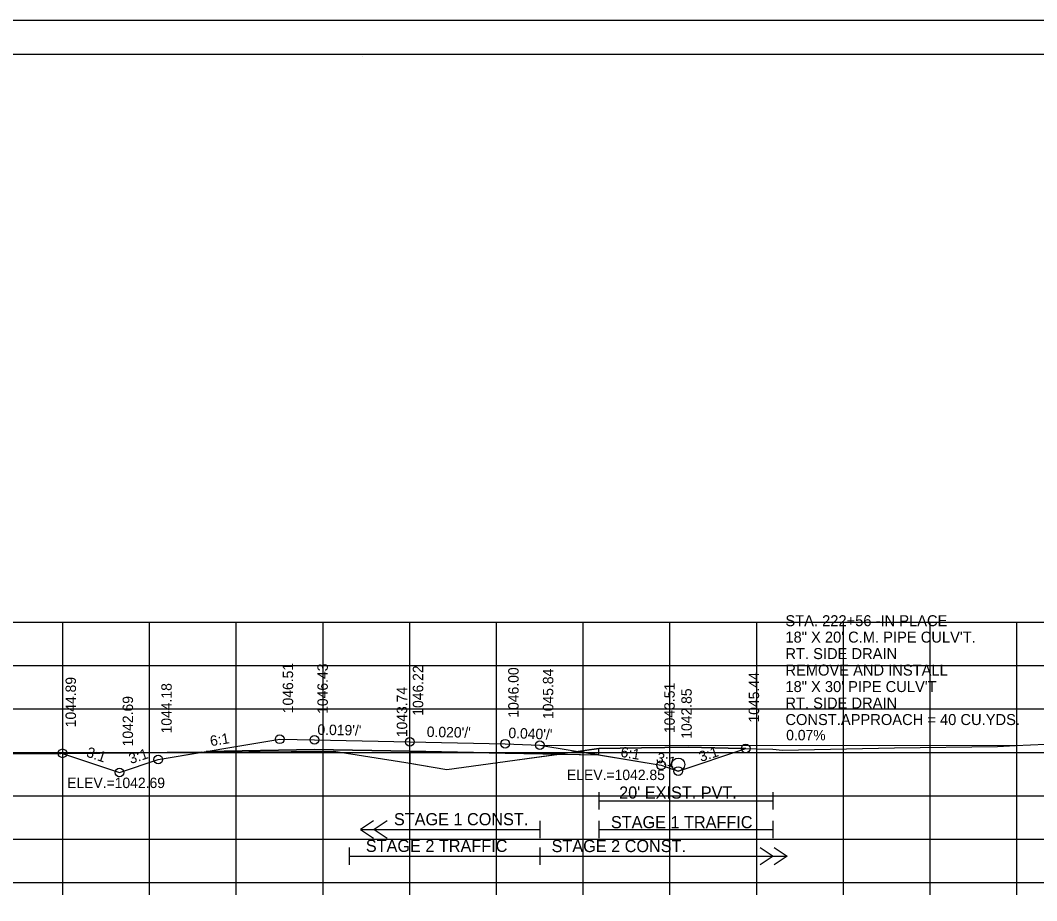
# Model space of a CAD drawing. Extents: x 1370565 to 1374448, y 301010 to 304637.
# Drawn here: x 1373323.9 to 1373441.1, y 303116.9 to 303218.4 of the extents above; entities that cross this region are included whole.
import ezdxf

# ---------------------------------------------------------------- set-up
doc = ezdxf.new("R2010")
doc.units = 0
for name, color, linetype in [('R_Alt Surface', 7, 'Continuous'), ('R_Axis', 7, 'Continuous'), ('R_Axis Annot', 7, 'Continuous'), ('R_Border', 7, 'Continuous'), ('R_Contours', 7, 'Continuous'), ('R_Drive', 7, 'Continuous'), ('R_Exist Surface', 7, 'Continuous'), ('R_Fin Surface', 7, 'Continuous'), ('R_Grid', 7, 'Continuous'), ('R_No Plot', 7, 'Continuous'), ('R_Water', 7, 'Continuous'), ('R_Water Annot', 7, 'Continuous'), ('R_Xsect Elev', 7, 'Continuous'), ('R_Xsect Slope', 7, 'Continuous')]:
    doc.layers.add(name, color=color, linetype=linetype)

msp = doc.modelspace()

# ---------------------------------------------------------------- linework, layer by layer
at = {"layer": 'R_Alt Surface'}
for points in [[(1373345.35, 303134.1), (1373357.81, 303134.35), (1373368.81, 303134.14), (1373379.81, 303133.92), (1373390.66, 303133.7)], [(1373364.62, 303126.12), (1373363.12, 303125.12), (1373364.62, 303124.12)], [(1373366.22, 303126.12), (1373364.72, 303125.12), (1373366.22, 303124.12)], [(1373363.12, 303125.12), (1373383.82, 303125.12)], [(1373361.82, 303123.05), (1373361.82, 303121.05)], [(1373383.82, 303123.05), (1373383.82, 303121.05)], [(1373383.82, 303123.05), (1373383.82, 303121.05)], [(1373409.22, 303123.05), (1373410.72, 303122.05), (1373409.22, 303121.05)], [(1373410.81, 303123.05), (1373412.31, 303122.05), (1373410.81, 303121.05)], [(1373361.82, 303122.05), (1373383.82, 303122.05)], [(1373383.82, 303122.05), (1373412.31, 303122.05)]]:
    msp.add_lwpolyline(points, dxfattribs=at)
at = {"layer": 'R_Axis'}
for p, q in [((1373218.81, 303119), (1373518.81, 303119)), ((1373328.81, 303117.6), (1373328.81, 303119)), ((1373338.81, 303117.6), (1373338.81, 303119)), ((1373348.81, 303117.6), (1373348.81, 303119)), ((1373358.81, 303117.6), (1373358.81, 303119)), ((1373368.81, 303117.6), (1373368.81, 303119)), ((1373378.81, 303117.6), (1373378.81, 303119)), ((1373388.81, 303117.6), (1373388.81, 303119)), ((1373398.81, 303117.6), (1373398.81, 303119)), ((1373408.81, 303117.6), (1373408.81, 303119)), ((1373418.81, 303117.6), (1373418.81, 303119)), ((1373428.81, 303117.6), (1373428.81, 303119)), ((1373438.81, 303117.6), (1373438.81, 303119))]:
    msp.add_line(p, q, dxfattribs=at)
for points in [[(1373390.62, 303129.43), (1373390.62, 303127.43)], [(1373390.62, 303128.43), (1373410.67, 303128.43)], [(1373410.67, 303129.43), (1373410.67, 303127.43)], [(1373383.82, 303126.12), (1373383.82, 303124.12)], [(1373390.62, 303126.12), (1373390.62, 303124.12)], [(1373410.67, 303126.12), (1373410.67, 303124.12)], [(1373390.62, 303125.12), (1373410.67, 303125.12)]]:
    msp.add_lwpolyline(points, dxfattribs=at)
at = {"layer": 'R_Border'}
for p, q in [((1373210.81, 303214.46), (1373526.99, 303214.46)), ((1373363.33, 303214.2), (1373363.33, 303214.2)), ((1373363.33, 303214.2), (1373363.33, 303214.2))]:
    msp.add_line(p, q, dxfattribs=at)
at = {"layer": 'R_Contours'}
for p, q in [((1373390.62, 303133.71), (1373390.62, 303134.43)), ((1373344.83, 303134.02), (1373328.77, 303133.89)), ((1373345.35, 303134.02), (1373360.04, 303134.14)), ((1373379.81, 303133.92), (1373368.81, 303134.14)), ((1373368.81, 303134.14), (1373368.81, 303132.75)), ((1373368.81, 303132.75), (1373368.81, 303134.14)), ((1373386.02, 303133.79), (1373379.81, 303133.92)), ((1373388.24, 303134.1), (1373386.02, 303133.79)), ((1373386.02, 303133.79), (1373390.66, 303133.7)), ((1373390.66, 303133.7), (1373388.24, 303134.1))]:
    msp.add_line(p, q, dxfattribs=at)
for points in [[(1373368.81, 303134.14), (1373357.81, 303134.35), (1373345.35, 303134.1)], [(1373407.54, 303134.44), (1373407.05, 303134.46), (1373400.91, 303134.61), (1373395.51, 303134.52), (1373390.62, 303134.43), (1373388.24, 303134.1)], [(1373397.81, 303132.51), (1373399.77, 303131.85), (1373407.54, 303134.44)], [(1373328.77, 303133.89), (1373335.35, 303131.69), (1373339.81, 303133.18), (1373344.83, 303134.02)], [(1373345.35, 303134.1), (1373345.35, 303134.02)], [(1373360.04, 303134.14), (1373368.35, 303132.82), (1373368.81, 303132.75)], [(1373368.81, 303132.75), (1373373.07, 303132.03), (1373380.91, 303133.09), (1373386.02, 303133.79)], [(1373388.24, 303134.1), (1373390.66, 303133.7), (1373397.81, 303132.51)]]:
    msp.add_lwpolyline(points, dxfattribs=at)
at = {"layer": 'R_Drive'}
msp.add_line((1373383.81, 303134.84), (1373438.65, 303134.81), dxfattribs=at)
at = {"layer": 'R_Exist Surface'}
msp.add_lwpolyline([(1373302.68, 303133.71), (1373328.59, 303133.89), (1373360.04, 303134.14), (1373368.35, 303132.82), (1373373.07, 303132.03), (1373380.91, 303133.09), (1373390.62, 303134.43), (1373395.51, 303134.52), (1373400.91, 303134.61), (1373407.05, 303134.46), (1373410.67, 303134.37), (1373411.77, 303134.24), (1373424.7, 303134.54), (1373436.57, 303134.69), (1373438.65, 303134.81), (1373442.1, 303134.96), (1373465.12, 303136.2), (1373490.59, 303136.94), (1373497.19, 303136.91), (1373509.16, 303137.23), (1373515.15, 303137.34), (1373516.66, 303137.37), (1373518.81, 303137.34)], dxfattribs=at)
at = {"layer": 'R_Fin Surface'}
msp.add_lwpolyline([(1373328.77, 303133.89), (1373335.35, 303131.69), (1373339.81, 303133.18), (1373353.81, 303135.51), (1373357.81, 303135.44), (1373368.81, 303135.22), (1373379.81, 303135), (1373383.81, 303134.84), (1373397.81, 303132.51), (1373399.77, 303131.85), (1373407.54, 303134.44)], dxfattribs=at)
at = {"layer": 'R_Grid'}
for p, q in [((1373218.81, 303149), (1373518.81, 303149)), ((1373328.81, 303119), (1373328.81, 303149)), ((1373338.81, 303119), (1373338.81, 303149)), ((1373348.81, 303119), (1373348.81, 303149)), ((1373358.81, 303119), (1373358.81, 303149)), ((1373368.81, 303119), (1373368.81, 303149)), ((1373378.81, 303119), (1373378.81, 303149)), ((1373388.81, 303119), (1373388.81, 303149)), ((1373398.81, 303119), (1373398.81, 303149)), ((1373408.81, 303119), (1373408.81, 303149)), ((1373418.81, 303119), (1373418.81, 303149)), ((1373428.81, 303119), (1373428.81, 303149)), ((1373438.81, 303119), (1373438.81, 303149)), ((1373218.81, 303144), (1373518.81, 303144)), ((1373218.81, 303139), (1373518.81, 303139)), ((1373218.81, 303134), (1373518.81, 303134)), ((1373218.81, 303129), (1373518.81, 303129)), ((1373218.81, 303124), (1373518.81, 303124)), ((1373218.81, 303119), (1373518.81, 303119))]:
    msp.add_line(p, q, dxfattribs=at)
at = {"layer": 'R_No Plot'}
msp.add_line((1373198.41, 303218.36), (1373531.75, 303218.36), dxfattribs=at)
for points in [[(1373198.41, 303218.36), (1373531.75, 303218.36), (1373531.75, 303005.02), (1373198.41, 303005.02)], [(1373444.73, 303214.46), (1373464.35, 303214.46), (1373464.35, 303204.58), (1373480.47, 303204.58), (1373503.67, 303204.58), (1373503.67, 303180.25), (1373526.99, 303180.25), (1373526.99, 303009), (1373210.81, 303009), (1373210.81, 303214.46)]]:
    msp.add_lwpolyline(points, close=True, dxfattribs=at)
for centre in [(1373353.81, 303135.51), (1373357.81, 303135.44), (1373368.81, 303135.22), (1373379.81, 303135), (1373328.77, 303133.89), (1373383.81, 303134.84), (1373407.54, 303134.44), (1373339.81, 303133.18), (1373335.35, 303131.69), (1373397.81, 303132.51), (1373399.77, 303131.85)]:
    msp.add_circle(centre, 0.5, dxfattribs=at)
at = {"layer": 'R_Water'}
msp.add_circle((1373399.77, 303132.6), 0.75, dxfattribs=at)
at = {"layer": 'R_Xsect Elev'}
msp.add_line((1373368.81, 303132.75), (1373368.81, 303142.75), dxfattribs=at)

# ---------------------------------------------------------------- texts
at = {"layer": 'R_Axis Annot'}
msp.add_text("20' EXIST. PVT.", height=1.4, dxfattribs=at).set_placement((1373392.95, 303128.67))
at = {"layer": 'R_Water'}
for s, p in [('STAGE 1 CONST.', (1373366.98, 303125.6)), ('STAGE 1 TRAFFIC', (1373392, 303125.26)), ('STAGE 2 TRAFFIC', (1373363.74, 303122.53)), ('STAGE 2 CONST.', (1373385.16, 303122.51))]:
    msp.add_text(s, height=1.4, dxfattribs=at).set_placement(p)
at = {"layer": 'R_Water Annot'}
for s, p in [('STA. 222+56 -IN PLACE ', (1373412.12, 303148.54)), ('18" X 20\' C.M. PIPE CULV\'T.', (1373412.12, 303146.65)), ('RT. SIDE DRAIN', (1373412.12, 303144.75)), ('REMOVE AND INSTALL', (1373412.12, 303142.85)), ('18" X 30\' PIPE CULV\'T', (1373412.12, 303140.95)), ('RT. SIDE DRAIN', (1373412.12, 303139.05)), ('CONST.APPROACH = 40 CU.YDS.', (1373412.12, 303137.15))]:
    msp.add_text(s, height=1.2661, dxfattribs=at).set_placement(p)
at = {"layer": 'R_Xsect Elev'}
for s, rotation, p in [('1046.51', 90, (1373355.36, 303138.51)), ('1046.43', 90, (1373359.36, 303138.44)), ('1046.22', 90, (1373370.36, 303138.22)), ('1046.00', 90, (1373381.36, 303138)), ('1044.89', 90, (1373330.32, 303136.89)), ('1045.84', 90, (1373385.36, 303137.84)), ('1045.44', 90, (1373409.09, 303137.44)), ('1044.18', 90, (1373341.36, 303136.18)), ('1043.74', 90, (1373368.51, 303135.75)), ('1043.51', 90, (1373399.36, 303136.22)), ('1042.69', 90, (1373336.9, 303134.69)), ('1042.85', 90, (1373401.32, 303135.57)), ('0.07%', 359.9627, (1373412.21, 303135.39))]:
    msp.add_text(s, height=1.2, rotation=rotation, dxfattribs=at).set_placement(p)
for s, p in [('ELEV.=1042.85', (1373386.94, 303130.81)), ('ELEV.=1042.69', (1373329.3, 303129.89))]:
    msp.add_text(s, height=1.2, dxfattribs=at).set_placement(p)
at = {"layer": 'R_Xsect Slope'}
for s, rotation, p in [("0.019'/'", 358.885, (1373358.15, 303136.03)), ("0.020'/'", 358.8542, (1373370.76, 303135.78)), ("0.040'/'", 357.7094, (1373380.16, 303135.66)), ('6:1', 9.4623, (1373345.88, 303134.7)), ('3:1', 341.5668, (1373331.43, 303133.53)), ('3:1', 18.4349, (1373336.64, 303132.65)), ('6:1', 350.5377, (1373393.05, 303133.5)), ('3:1', 18.4332, (1373402.39, 303132.89)), ('3:1', 341.5651, (1373397.12, 303132.92))]:
    msp.add_text(s, height=1.2, rotation=rotation, dxfattribs=at).set_placement(p)

doc.saveas('drawing.dxf')
